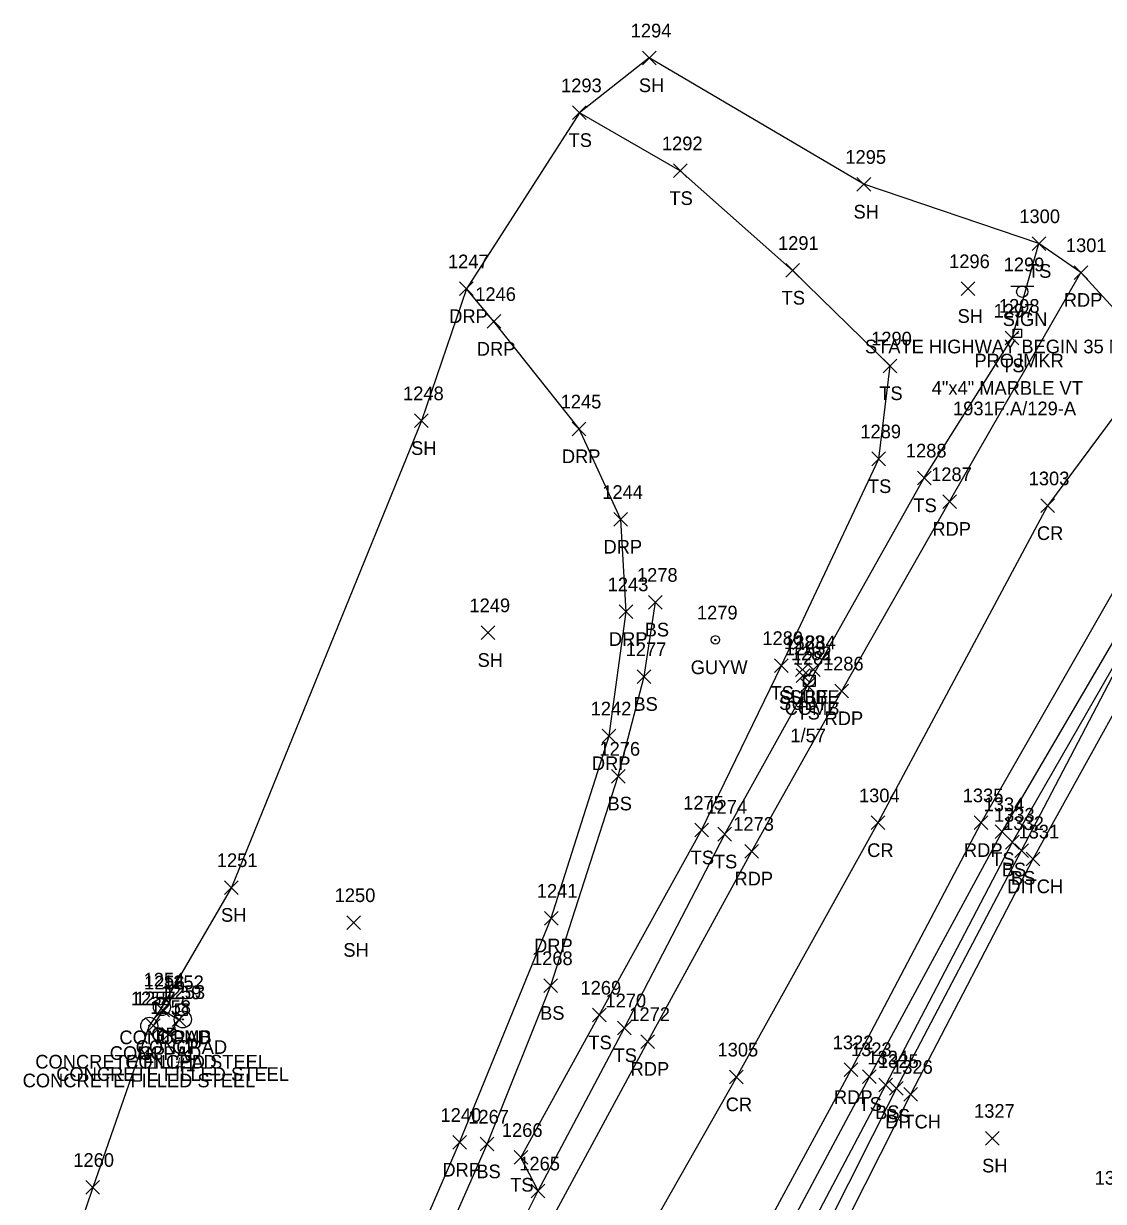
# Model space of a CAD drawing. Extents: x 1639430 to 1640195, y 612006 to 612917.
# Drawn here: x 1639822.3 to 1639980.2, y 612744.6 to 612916.9 of the extents above; entities that cross this region are included whole.
import ezdxf

# ---------------------------------------------------------------- set-up
doc = ezdxf.new("R2010")
doc.units = 0
for name, color, linetype in [('D_A', 7, 'Continuous'), ('D_I', 7, 'Continuous'), ('D_TIC', 7, 'Continuous'), ('DD', 7, 'Continuous'), ('L_A', 7, 'Continuous'), ('L_I', 7, 'Continuous'), ('L_TIC', 7, 'Continuous'), ('LELB', 7, 'Continuous'), ('LS', 7, 'Continuous'), ('LSOGP', 7, 'Continuous'), ('P_A', 7, 'Continuous'), ('P_I', 7, 'Continuous'), ('P_TIC', 7, 'Continuous'), ('PET', 7, 'Continuous'), ('PRC', 7, 'Continuous'), ('R_A', 7, 'Continuous'), ('R_C', 7, 'Continuous'), ('R_I', 7, 'Continuous'), ('R_TIC', 7, 'Continuous'), ('RDP', 7, 'Continuous'), ('RGP', 7, 'Continuous'), ('S_A', 7, 'Continuous'), ('S_C', 7, 'Continuous'), ('S_I', 7, 'Continuous'), ('SRM', 7, 'Continuous'), ('SSGN', 7, 'Continuous'), ('U_A', 7, 'Continuous'), ('U_C', 7, 'Continuous'), ('U_I', 7, 'Continuous'), ('U_TIC', 7, 'Continuous'), ('UP', 7, 'Continuous'), ('UPGW', 7, 'Continuous')]:
    doc.layers.add(name, color=color, linetype=linetype)

msp = doc.modelspace()

# ---------------------------------------------------------------- linework, layer by layer
at = {"layer": 'D_TIC'}
for points in [[(1639968.9, 612793.69), (1639970.9, 612795.69)], [(1639970.9, 612793.69), (1639968.9, 612795.69)], [(1639951.02, 612759.27), (1639953.02, 612761.27)], [(1639953.02, 612759.27), (1639951.02, 612761.27)]]:
    msp.add_lwpolyline(points, dxfattribs=at)
at = {"layer": 'DD'}
msp.add_lwpolyline([(1639927.28, 612709.49), (1639934.25, 612725.09), (1639952.02, 612760.27), (1639969.9, 612794.69), (1639991.51, 612833.72), (1640000.55, 612849.98), (1639999.06, 612851.35), (1640004.27, 612861.49)], dxfattribs=at)
at = {"layer": 'L_TIC'}
for points in [[(1639912.76, 612910.86), (1639914.76, 612912.86)], [(1639914.76, 612910.86), (1639912.76, 612912.86)], [(1639902.56, 612902.84), (1639904.56, 612904.84)], [(1639904.56, 612902.84), (1639902.56, 612904.84)], [(1639917.31, 612894.35), (1639919.31, 612896.35)], [(1639919.31, 612894.35), (1639917.31, 612896.35)], [(1639944.15, 612892.37), (1639946.15, 612894.37)], [(1639946.15, 612892.37), (1639944.15, 612894.37)], [(1639969.75, 612883.7), (1639971.75, 612885.7)], [(1639971.75, 612883.7), (1639969.75, 612885.7)], [(1639933.72, 612879.78), (1639935.72, 612881.78)], [(1639935.72, 612879.78), (1639933.72, 612881.78)], [(1639959.37, 612877.11), (1639961.37, 612879.11)], [(1639961.37, 612877.11), (1639959.37, 612879.11)], [(1639965.82, 612869.89), (1639967.82, 612871.89)], [(1639967.82, 612869.89), (1639965.82, 612871.89)], [(1639948, 612865.81), (1639950, 612867.81)], [(1639950, 612865.81), (1639948, 612867.81)], [(1639879.45, 612857.79), (1639881.45, 612859.79)], [(1639881.45, 612857.79), (1639879.45, 612859.79)], [(1639946.34, 612852.22), (1639948.34, 612854.22)], [(1639948.34, 612852.22), (1639946.34, 612854.22)], [(1639952.99, 612849.42), (1639954.99, 612851.42)], [(1639954.99, 612849.42), (1639952.99, 612851.42)], [(1639913.66, 612831.24), (1639915.66, 612833.24)], [(1639915.66, 612831.24), (1639913.66, 612833.24)], [(1639889.17, 612826.79), (1639891.17, 612828.79)], [(1639891.17, 612826.79), (1639889.17, 612828.79)], [(1639932.09, 612821.99), (1639934.09, 612823.99)], [(1639934.09, 612821.99), (1639932.09, 612823.99)], [(1639912.01, 612820.36), (1639914.01, 612822.36)], [(1639914.01, 612820.36), (1639912.01, 612822.36)], [(1639935.89, 612819.09), (1639937.89, 612821.09)], [(1639937.89, 612819.09), (1639935.89, 612821.09)], [(1639908.23, 612805.8), (1639910.23, 612807.8)], [(1639910.23, 612805.8), (1639908.23, 612807.8)], [(1639920.42, 612797.91), (1639922.42, 612799.91)], [(1639922.42, 612797.91), (1639920.42, 612799.91)], [(1639923.81, 612797.32), (1639925.81, 612799.32)], [(1639925.81, 612797.32), (1639923.81, 612799.32)], [(1639964.37, 612797.68), (1639966.37, 612799.68)], [(1639966.37, 612797.68), (1639964.37, 612799.68)], [(1639965.87, 612796.15), (1639967.87, 612798.15)], [(1639967.87, 612796.15), (1639965.87, 612798.15)], [(1639967.23, 612794.93), (1639969.23, 612796.93)], [(1639969.23, 612794.93), (1639967.23, 612796.93)], [(1639851.66, 612789.51), (1639853.66, 612791.51)], [(1639853.66, 612789.51), (1639851.66, 612791.51)], [(1639869.54, 612784.39), (1639871.54, 612786.39)], [(1639871.54, 612784.39), (1639869.54, 612786.39)], [(1639898.36, 612775.17), (1639900.36, 612777.17)], [(1639900.36, 612775.17), (1639898.36, 612777.17)], [(1639841.63, 612771.6), (1639843.63, 612773.6)], [(1639843.63, 612771.6), (1639841.63, 612773.6)], [(1639841.63, 612771.6), (1639843.63, 612773.6)], [(1639843.63, 612771.6), (1639841.63, 612773.6)], [(1639840.23, 612769.3), (1639842.23, 612771.3)], [(1639842.23, 612769.3), (1639840.23, 612771.3)], [(1639844.01, 612770.18), (1639846.01, 612772.18)], [(1639846.01, 612770.18), (1639844.01, 612772.18)], [(1639844.01, 612770.18), (1639846.01, 612772.18)], [(1639846.01, 612770.18), (1639844.01, 612772.18)], [(1639905.46, 612770.85), (1639907.46, 612772.85)], [(1639907.46, 612770.85), (1639905.46, 612772.85)], [(1639842.5, 612768.02), (1639844.5, 612770.02)], [(1639844.5, 612768.02), (1639842.5, 612770.02)], [(1639909.14, 612768.99), (1639911.14, 612770.99)], [(1639911.14, 612768.99), (1639909.14, 612770.99)], [(1639944.96, 612761.85), (1639946.96, 612763.85)], [(1639946.96, 612761.85), (1639944.96, 612763.85)], [(1639947.36, 612760.64), (1639949.36, 612762.64)], [(1639949.36, 612760.64), (1639947.36, 612762.64)], [(1639948.92, 612760.12), (1639950.92, 612762.12)], [(1639950.92, 612760.12), (1639948.92, 612762.12)], [(1639889.04, 612751.99), (1639891.04, 612753.99)], [(1639891.04, 612751.99), (1639889.04, 612753.99)], [(1639962.96, 612752.84), (1639964.96, 612754.84)], [(1639964.96, 612752.84), (1639962.96, 612754.84)], [(1639894.01, 612750.04), (1639896.01, 612752.04)], [(1639896.01, 612750.04), (1639894.01, 612752.04)], [(1639831.37, 612745.66), (1639833.37, 612747.66)], [(1639833.37, 612745.66), (1639831.37, 612747.66)], [(1639896.5, 612745.14), (1639898.5, 612747.14)], [(1639898.5, 612745.14), (1639896.5, 612747.14)], [(1639896.5, 612745.14), (1639898.5, 612747.14)], [(1639898.5, 612745.14), (1639896.5, 612747.14)]]:
    msp.add_lwpolyline(points, dxfattribs=at)
at = {"layer": 'LELB'}
for points in [[(1639897.5, 612746.14), (1639895.01, 612751.04), (1639906.46, 612771.85), (1639921.42, 612798.91), (1639933.09, 612822.99), (1639947.34, 612853.22), (1639949, 612866.81), (1639934.72, 612880.78), (1639918.31, 612895.35), (1639903.56, 612903.84)], [(1639881.2, 612732.85), (1639886.51, 612728.85), (1639891.05, 612733.19), (1639897.5, 612746.14), (1639910.14, 612769.99), (1639924.81, 612798.32), (1639936.89, 612820.09), (1639953.99, 612850.42), (1639966.82, 612870.89), (1639970.75, 612884.7)], [(1639920.56, 612713.35), (1639928.08, 612729.31), (1639945.96, 612762.85), (1639965.37, 612798.68), (1639987.12, 612835.84), (1639996.31, 612853.13)], [(1639923.98, 612711.48), (1639930.58, 612727.96), (1639948.36, 612761.64), (1639966.87, 612797.15), (1639988.64, 612835), (1639997.99, 612851.89)], [(1639925.69, 612710.85), (1639932.54, 612726.53), (1639949.92, 612761.12), (1639968.23, 612795.93), (1639988.64, 612835)], [(1639881.2, 612732.85), (1639890.04, 612752.99), (1639899.36, 612776.17), (1639909.23, 612806.8), (1639913.01, 612821.36), (1639914.66, 612832.24)]]:
    msp.add_lwpolyline(points, dxfattribs=at)
at = {"layer": 'LS'}
for points in [[(1639842.63, 612772.6), (1639841.23, 612770.3), (1639843.5, 612769.02), (1639845.01, 612771.18)], [(1639842.63, 612772.6), (1639845.01, 612771.18)]]:
    msp.add_lwpolyline(points, dxfattribs=at)
at = {"layer": 'LSOGP'}
msp.add_lwpolyline([(1639988.18, 612868.16), (1639976.9, 612880.46), (1639970.75, 612884.7), (1639945.15, 612893.38), (1639913.76, 612911.86), (1639903.56, 612903.84), (1639887.02, 612878.09), (1639880.45, 612858.79), (1639852.65, 612790.52), (1639842.5, 612773.04), (1639840.65, 612770.29), (1639832.37, 612746.66), (1639825.6, 612726.67)], dxfattribs=at)
at = {"layer": 'P_TIC'}
for points in [[(1639975.9, 612879.46), (1639977.9, 612881.46)], [(1639977.9, 612879.46), (1639975.9, 612881.46)], [(1639956.68, 612845.96), (1639958.68, 612847.96)], [(1639958.68, 612845.96), (1639956.68, 612847.96)], [(1639971.03, 612845.35), (1639973.03, 612847.35)], [(1639973.03, 612845.35), (1639971.03, 612847.35)], [(1639940.92, 612818.27), (1639942.92, 612820.27)], [(1639942.92, 612818.27), (1639940.92, 612820.27)], [(1639946.21, 612798.98), (1639948.21, 612800.98)], [(1639948.21, 612798.98), (1639946.21, 612800.98)], [(1639961.3, 612798.99), (1639963.3, 612800.99)], [(1639963.3, 612798.99), (1639961.3, 612800.99)], [(1639927.75, 612794.82), (1639929.75, 612796.82)], [(1639929.75, 612794.82), (1639927.75, 612796.82)], [(1639912.55, 612766.99), (1639914.55, 612768.99)], [(1639914.55, 612766.99), (1639912.55, 612768.99)], [(1639942.29, 612762.86), (1639944.29, 612764.86)], [(1639944.29, 612762.86), (1639942.29, 612764.86)], [(1639925.52, 612761.8), (1639927.52, 612763.8)], [(1639927.52, 612761.8), (1639925.52, 612763.8)]]:
    msp.add_lwpolyline(points, dxfattribs=at)
at = {"layer": 'PET'}
for points in [[(1639897.29, 612737.85), (1639913.55, 612767.99), (1639928.75, 612795.82), (1639941.92, 612819.27), (1639957.68, 612846.96), (1639976.9, 612880.46)], [(1639918, 612716.74), (1639925.91, 612731.74), (1639943.29, 612763.86), (1639962.3, 612799.99), (1639983.33, 612836.7), (1639995.21, 612854.18), (1640002.09, 612863.22)]]:
    msp.add_lwpolyline(points, dxfattribs=at)
at = {"layer": 'PRC'}
msp.add_lwpolyline([(1639988.18, 612868.16), (1639972.03, 612846.35), (1639947.21, 612799.98), (1639926.52, 612762.8), (1639908.46, 612730.93)], dxfattribs=at)
at = {"layer": 'R_TIC'}
for points in [[(1639886.02, 612877.09), (1639888.02, 612879.09)], [(1639888.02, 612877.09), (1639886.02, 612879.09)], [(1639890.06, 612872.31), (1639892.06, 612874.31)], [(1639892.06, 612872.31), (1639890.06, 612874.31)], [(1639902.5, 612856.59), (1639904.5, 612858.59)], [(1639904.5, 612856.59), (1639902.5, 612858.59)], [(1639908.6, 612843.36), (1639910.6, 612845.36)], [(1639910.6, 612843.36), (1639908.6, 612845.36)], [(1639909.39, 612829.86), (1639911.39, 612831.86)], [(1639911.39, 612829.86), (1639909.39, 612831.86)], [(1639906.89, 612811.69), (1639908.89, 612813.69)], [(1639908.89, 612811.69), (1639906.89, 612813.69)], [(1639898.44, 612785.03), (1639900.44, 612787.03)], [(1639900.44, 612785.03), (1639898.44, 612787.03)], [(1639885.02, 612752.24), (1639887.02, 612754.24)], [(1639887.02, 612752.24), (1639885.02, 612754.24)]]:
    msp.add_lwpolyline(points, dxfattribs=at)
at = {"layer": 'RDP'}
msp.add_lwpolyline([(1639878.58, 612735.99), (1639886.02, 612753.24), (1639899.44, 612786.03), (1639907.89, 612812.69), (1639910.39, 612830.86), (1639909.6, 612844.36), (1639903.5, 612857.59), (1639891.06, 612873.31), (1639887.02, 612878.09)], dxfattribs=at)
at = {"layer": 'RGP'}
for p, q in [((1639842.5, 612773.04), (1639842.5, 612773.04)), ((1639845.56, 612771.23), (1639845.56, 612771.23)), ((1639840.65, 612770.29), (1639840.65, 612770.29))]:
    msp.add_line(p, q, dxfattribs=at)
for centre, radius in [((1639842.5, 612773.04), 1.25), ((1639842.5, 612773.04), 0.0833), ((1639840.65, 612770.29), 1.25), ((1639845.56, 612771.23), 1.25), ((1639845.56, 612771.23), 0.0833), ((1639840.65, 612770.29), 0.0833)]:
    msp.add_circle(centre, radius, dxfattribs=at)
at = {"layer": 'SRM'}
msp.add_lwpolyline([(1639966.97, 612872.21), (1639968.22, 612872.21), (1639968.22, 612870.96), (1639966.97, 612870.96)], close=True, dxfattribs=at)
msp.add_circle((1639967.59, 612871.59), 0.0833, dxfattribs=at)
at = {"layer": 'SSGN'}
for p, q in [((1639966.67, 612878.5), (1639970, 612878.5)), ((1639968.32, 612877.67), (1639968.32, 612877.67))]:
    msp.add_line(p, q, dxfattribs=at)
msp.add_circle((1639968.32, 612877.67), 0.833, dxfattribs=at)
at = {"layer": 'U_TIC'}
for points in [[(1639935.18, 612821.39), (1639937.18, 612823.39)], [(1639937.18, 612821.39), (1639935.18, 612823.39)], [(1639936.78, 612821.37), (1639938.78, 612823.37)], [(1639938.78, 612821.37), (1639936.78, 612823.37)], [(1639935.26, 612820.49), (1639937.26, 612822.49)], [(1639937.26, 612820.49), (1639935.26, 612822.49)]]:
    msp.add_lwpolyline(points, dxfattribs=at)
at = {"layer": 'UP'}
for p, q in [((1639936.35, 612819.93), (1639936.35, 612821.6)), ((1639936.35, 612821.6), (1639938.02, 612821.6)), ((1639937.44, 612822.43), (1639937.19, 612821.6)), ((1639938.02, 612821.6), (1639938.02, 612819.93)), ((1639938.02, 612819.93), (1639936.35, 612819.93)), ((1639936.94, 612819.1), (1639937.19, 612819.93)), ((1639937.19, 612820.77), (1639937.19, 612820.77)), ((1639844.53, 612771.82), (1639844.53, 612773.48)), ((1639844.53, 612773.48), (1639846.19, 612773.48)), ((1639845.61, 612774.32), (1639845.36, 612773.48)), ((1639846.19, 612773.48), (1639846.19, 612771.82)), ((1639846.19, 612771.82), (1639844.53, 612771.82)), ((1639845.11, 612770.98), (1639845.36, 612771.82)), ((1639845.36, 612772.65), (1639845.36, 612772.65))]:
    msp.add_line(p, q, dxfattribs=at)
for centre in [(1639937.19, 612820.77), (1639845.36, 612772.65)]:
    msp.add_circle(centre, 0.833, dxfattribs=at)
at = {"layer": 'UPGW'}
for radius in [0.625, 0.0833]:
    msp.add_circle((1639923.44, 612826.73), radius, dxfattribs=at)

# ---------------------------------------------------------------- texts
at = {"layer": 'D_A'}
for p in [(1639966.13, 612789.69), (1639948.26, 612755.27)]:
    msp.add_text('DITCH', height=2, dxfattribs=at).set_placement(p)
at = {"layer": 'D_I'}
for s, p in [('1331', (1639967.77, 612797.69)), ('1326', (1639949.28, 612763.27))]:
    msp.add_text(s, height=2, dxfattribs=at).set_placement(p)
at = {"layer": 'L_A'}
for s, p in [('SH', (1639912.25, 612906.86)), ('TS', (1639901.97, 612898.84)), ('TS', (1639916.72, 612890.35)), ('SH', (1639943.64, 612888.37)), ('TS', (1639969.16, 612879.7)), ('TS', (1639933.13, 612875.78)), ('SH', (1639958.86, 612873.11)), ('TS', (1639965.23, 612865.89)), ('TS', (1639947.41, 612861.81)), ('SH', (1639878.94, 612853.79)), ('TS', (1639945.75, 612848.22)), ('TS', (1639952.4, 612845.42)), ('BS', (1639913.1, 612827.24)), ('SH', (1639888.66, 612822.79)), ('TS', (1639931.5, 612817.99)), ('BS', (1639911.45, 612816.36)), ('TS', (1639935.3, 612815.09)), ('BS', (1639907.67, 612801.8)), ('TS', (1639919.83, 612793.91)), ('TS', (1639923.22, 612793.32)), ('TS', (1639963.78, 612793.68)), ('BS', (1639965.31, 612792.15)), ('BS', (1639966.67, 612790.93)), ('SH', (1639851.14, 612785.51)), ('SH', (1639869.03, 612780.39)), ('BS', (1639897.8, 612771.17)), ('CONCPAD', (1639836.28, 612767.6)), ('CONCPAD', (1639836.28, 612767.6)), ('CONCPAD', (1639838.66, 612766.18)), ('CONCPAD', (1639838.66, 612766.18)), ('TS', (1639904.87, 612766.85)), ('CONCPAD', (1639834.87, 612765.3)), ('CONCPAD', (1639837.14, 612764.02)), ('TS', (1639908.55, 612764.99)), ('TS', (1639944.37, 612757.85)), ('BS', (1639946.8, 612756.64)), ('BS', (1639948.36, 612756.12)), ('SH', (1639962.45, 612748.84)), ('BS', (1639888.48, 612747.99)), ('TS', (1639893.42, 612746.04))]:
    msp.add_text(s, height=2, dxfattribs=at).set_placement(p)
at = {"layer": 'L_I'}
for s, p in [('1294', (1639911.06, 612914.86)), ('1293', (1639900.87, 612906.84)), ('1292', (1639915.62, 612898.35)), ('1295', (1639942.45, 612896.37)), ('1300', (1639967.89, 612887.7)), ('1291', (1639932.6, 612883.78)), ('1296', (1639957.62, 612881.11)), ('1297', (1639964.13, 612873.89)), ('1290', (1639946.22, 612869.81)), ('1248', (1639877.76, 612861.79)), ('1289', (1639944.64, 612856.22)), ('1288', (1639951.3, 612853.42)), ('1278', (1639911.97, 612835.24)), ('1249', (1639887.47, 612830.79)), ('1277', (1639910.32, 612824.36)), ('1280', (1639930.31, 612825.99)), ('1281', (1639934.76, 612823.09)), ('1276', (1639906.48, 612809.8)), ('1275', (1639918.73, 612801.91)), ('1274', (1639922.12, 612801.32)), ('1334', (1639962.67, 612801.68)), ('1333', (1639964.18, 612800.15)), ('1332', (1639965.53, 612798.93)), ('1251', (1639850.53, 612793.51)), ('1250', (1639867.76, 612788.39)), ('1268', (1639896.62, 612779.17)), ('1256', (1639839.89, 612775.6)), ('1256', (1639839.89, 612775.6)), ('1269', (1639903.71, 612774.85)), ('1257', (1639838.54, 612773.3)), ('1259', (1639842.31, 612774.18)), ('1259', (1639842.31, 612774.18)), ('1270', (1639907.36, 612772.99)), ('1258', (1639840.8, 612772.02)), ('1323', (1639943.27, 612765.85)), ('1324', (1639945.66, 612764.64)), ('1325', (1639947.22, 612764.12)), ('1267', (1639887.3, 612755.99)), ('1327', (1639961.27, 612756.84)), ('1266', (1639892.21, 612754.04)), ('1260', (1639829.54, 612749.66)), ('1265', (1639894.76, 612749.14)), ('1265', (1639894.76, 612749.14)), ('1328', (1639978.91, 612747.05))]:
    msp.add_text(s, height=2, dxfattribs=at).set_placement(p)
at = {"layer": 'P_A'}
for s, p in [('RDP', (1639974.39, 612875.46)), ('RDP', (1639955.17, 612841.96)), ('CR', (1639970.46, 612841.35)), ('RDP', (1639939.41, 612814.27)), ('CR', (1639945.64, 612794.98)), ('RDP', (1639959.79, 612794.99)), ('RDP', (1639926.23, 612790.82)), ('RDP', (1639911.04, 612762.99)), ('CR', (1639924.95, 612757.8)), ('RDP', (1639940.78, 612758.86))]:
    msp.add_text(s, height=2, dxfattribs=at).set_placement(p)
at = {"layer": 'P_I'}
for s, p in [('1301', (1639974.7, 612883.46)), ('1287', (1639954.99, 612849.96)), ('1303', (1639969.26, 612849.35)), ('1286', (1639939.17, 612822.27)), ('1304', (1639944.44, 612802.98)), ('1335', (1639959.61, 612802.99)), ('1273', (1639926.05, 612798.82)), ('1272', (1639910.85, 612770.99)), ('1305', (1639923.75, 612765.8)), ('1322', (1639940.6, 612766.86))]:
    msp.add_text(s, height=2, dxfattribs=at).set_placement(p)
at = {"layer": 'R_A'}
for s, p in [('DRP', (1639884.51, 612873.09)), ('DRP', (1639888.55, 612868.31)), ('DRP', (1639900.99, 612852.59)), ('DRP', (1639907.08, 612839.36)), ('DRP', (1639907.87, 612825.86)), ('DRP', (1639905.38, 612807.69)), ('DRP', (1639896.93, 612781.03)), ('GP', (1639840.93, 612768.04)), ('GP', (1639843.99, 612766.23)), ('GP', (1639839.08, 612765.29)), ('DRP', (1639883.51, 612748.24))]:
    msp.add_text(s, height=2, dxfattribs=at).set_placement(p)
at = {"layer": 'R_C'}
for p in [(1639823.98, 612764.04), (1639822.13, 612761.29), (1639827.04, 612762.23)]:
    msp.add_text('CONCRETE FILLED STEEL', height=2, dxfattribs=at).set_placement(p)
at = {"layer": 'R_I'}
for s, p in [('1247', (1639884.33, 612881.09)), ('1246', (1639888.32, 612876.31)), ('1245', (1639900.81, 612860.59)), ('1244', (1639906.9, 612847.36)), ('1243', (1639907.69, 612833.86)), ('1242', (1639905.2, 612815.69)), ('1241', (1639897.32, 612789.03)), ('1254', (1639839.81, 612776.04)), ('1255', (1639837.95, 612773.29)), ('1253', (1639842.86, 612774.23)), ('1240', (1639883.24, 612756.24))]:
    msp.add_text(s, height=2, dxfattribs=at).set_placement(p)
at = {"layer": 'S_A'}
for s, p in [('SIGN', (1639965.46, 612872.65)), ('PROJMKR', (1639961.32, 612866.59))]:
    msp.add_text(s, height=2, dxfattribs=at).set_placement(p)
at = {"layer": 'S_C'}
for s, p in [('STATE HIGHWAY BEGIN 35 MPH', (1639945.31, 612868.65)), ('4"x4" MARBLE VT', (1639955.08, 612862.59)), ('1931F.A/129-A', (1639958.2, 612859.59))]:
    msp.add_text(s, height=2, dxfattribs=at).set_placement(p)
at = {"layer": 'S_I'}
for s, p in [('1299', (1639965.6, 612880.65)), ('1298', (1639964.9, 612874.59))]:
    msp.add_text(s, height=2, dxfattribs=at).set_placement(p)
at = {"layer": 'U_A'}
for s, p in [('GUYW', (1639919.83, 612821.73)), ('SUBE', (1639932.72, 612817.39)), ('SUBT', (1639932.76, 612816.49)), ('COMB', (1639933.57, 612815.77)), ('SUBE', (1639934.32, 612817.37)), ('COMB', (1639841.75, 612767.65))]:
    msp.add_text(s, height=2, dxfattribs=at).set_placement(p)
at = {"layer": 'U_C'}
for s, p in [('1/57', (1639934.41, 612811.77)), ('#1', (1639844.46, 612763.65))]:
    msp.add_text(s, height=2, dxfattribs=at).set_placement(p)
at = {"layer": 'U_I'}
for s, p in [('1279', (1639920.74, 612829.73)), ('1283', (1639933.49, 612825.39)), ('1285', (1639933.57, 612824.49)), ('1284', (1639935.09, 612825.37)), ('1282', (1639934.49, 612823.77)), ('1252', (1639842.67, 612775.65))]:
    msp.add_text(s, height=2, dxfattribs=at).set_placement(p)

doc.saveas('drawing.dxf')
